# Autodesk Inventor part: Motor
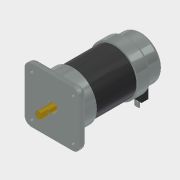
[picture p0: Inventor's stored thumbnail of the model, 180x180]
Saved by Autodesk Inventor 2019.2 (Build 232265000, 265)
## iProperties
Created: 2005-11
Part Number: Motor
Document SubType Name: Modeling
Designer: floress
Material: Default
Density: 1 g/cm^3
Appearance: Zinc
Author: floress
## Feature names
1. Extrusion1
2. Extrusion2
3. Extrusion3
4. Extrusion4
5. Extrusion5
6. Extrusion6
7. Extrusion7
8. Extrusion8
9. Extrusion9
10. Extrusion10
11. Extrusion11
12. Sweep1
13. Fillet2
14. Chamfer3
15. Chamfer4
16. Fillet3
## Parameters: d0 = 44.45 mm, d1 = 12.7 mm, d2 = 0, d3 = 41.275 mm, d4 = 38.1 mm, d5 = 0, d6 = 44.45 mm, d7 = 19.05 mm, d8 = 0, d9 = 9.525 mm, d10 = 12.7 mm, d11 = 0, d12 = 6.35 mm, d13 = 25.4 mm, d14 = 0, d15 = 6.35 mm, d16 = 0, d17 = 12.7 mm, d18 = 3.556 mm, d19 = 6.35 mm, d20 = 0, d21 = 12.7 mm, d22 = 0, d23 = 25.4 mm, d24 = 6.35 mm, d25 = 0, d29 = 4.7498 mm, d30 = 0.508 mm, d31 = 7.62 mm, d32 = 0, d39 = 1.397 mm, d42 = 0.762 mm, d43 = 0, d52 = 50.8 mm, d53 = 4.7625 mm, d54 = 0, d55 = 3.175 mm, d56 = 0.2032 mm, d57 = 3.175 mm, d58 = 45 deg, d59 = 0.79375 mm, d60 = 3.175 mm, d61 = 45 deg, d62 = 1.5875 mm, d63 = 0
